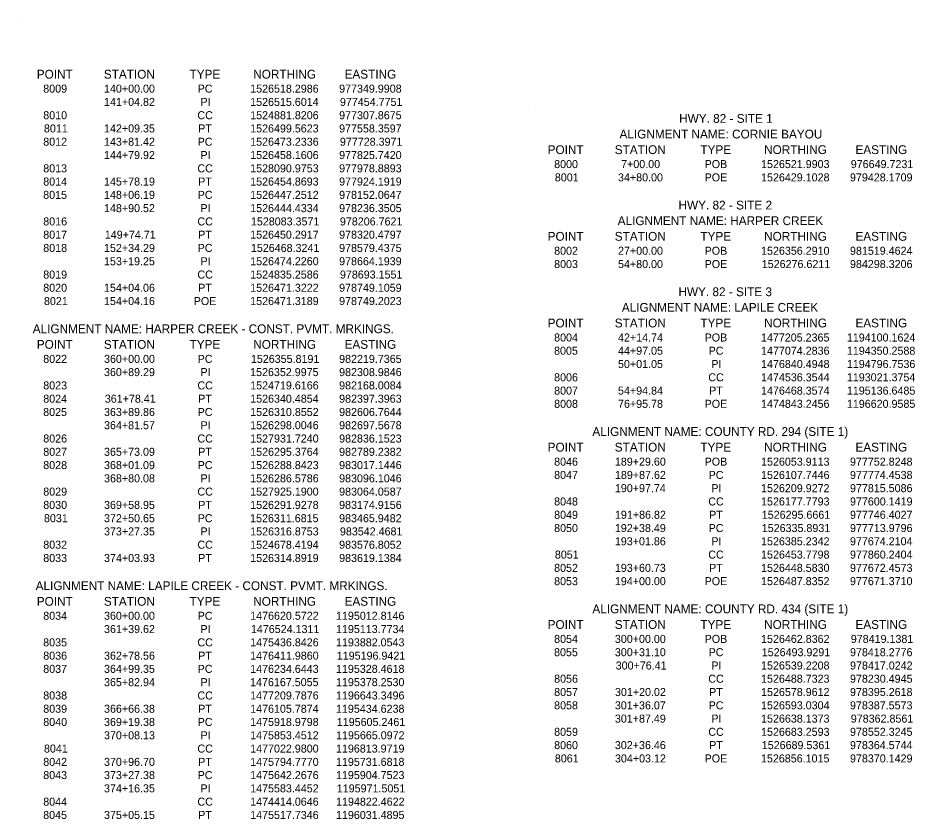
# Model space of a CAD drawing. Extents: x 977669 to 1196358, y 1472413 to 1526490.
# Drawn here: x 1193267 to 1194387, y 1472473 to 1473473 of the extents above; entities that cross this region are included whole.
import ezdxf

# ---------------------------------------------------------------- set-up
doc = ezdxf.new("R2010")
doc.units = 0
doc.layers.add('Default', color=7, linetype='Continuous')
doc.layers.add('R_Border', color=7, linetype='Continuous')

msp = doc.modelspace()

# ---------------------------------------------------------------- linework, layer by layer
at = {"layer": 'R_Border'}
for p, q in [((1193266.6, 1473473.4), (1193266.6, 1473473.4)), ((1193904.8, 1473357.8), (1193904.8, 1473357.8))]:
    msp.add_line(p, q, dxfattribs=at)

# ---------------------------------------------------------------- texts
at = {"layer": 'Default'}
for s, height, p in [('POINT', 11, (1193290.1, 1473397.7)), ('STATION', 11, (1193373.9, 1473397.7)), ('TYPE', 11, (1193480.9, 1473397.7)), ('NORTHING', 11, (1193560.5, 1473397.7)), ('EASTING', 11, (1193674.6, 1473397.7)), ('8009', 10, (1193298.2, 1473380.2)), ('140+00.00', 10, (1193374.1, 1473380.2)), ('PC', 10, (1193491.1, 1473380.2)), ('1526518.2986', 10, (1193556.7, 1473380.2)), ('977349.9908', 10, (1193667.8, 1473380.2)), ('141+04.82', 10, (1193374.1, 1473363.6)), ('PI', 10, (1193494.6, 1473363.6)), ('1526515.6014', 10, (1193556.7, 1473363.6)), ('977454.7751', 10, (1193668.8, 1473363.6)), ('8010', 10, (1193298.2, 1473347)), ('CC', 10, (1193490.8, 1473347)), ('1524881.8206', 10, (1193556.7, 1473347)), ('977307.8675', 10, (1193667.8, 1473347)), ('HWY. 82 - SITE 1', 11, (1194092.6, 1473342.5)), ('8011', 10, (1193299.1, 1473330.5)), ('142+09.35', 10, (1193374.1, 1473330.5)), ('PT', 10, (1193491.8, 1473330.5)), ('1526499.5623', 10, (1193556.7, 1473330.5)), ('977558.3597', 10, (1193667.8, 1473330.5)), ('ALIGNMENT NAME: CORNIE BAYOU', 11, (1194018.1, 1473323)), ('8012', 10, (1193298.2, 1473313.9)), ('143+81.42', 10, (1193374.1, 1473313.9)), ('PC', 10, (1193491.1, 1473313.9)), ('1526473.2336', 10, (1193556.7, 1473313.9)), ('977728.3971', 10, (1193668.8, 1473313.9)), ('POINT', 11, (1193928.3, 1473303.5)), ('STATION', 11, (1194012.1, 1473303.5)), ('TYPE', 11, (1194119.1, 1473303.5)), ('NORTHING', 11, (1194198.7, 1473303.5)), ('EASTING', 11, (1194312.8, 1473303.5)), ('144+79.92', 10, (1193374.1, 1473297.3)), ('PI', 10, (1193494.6, 1473297.3)), ('1526458.1606', 10, (1193556.7, 1473297.3)), ('977825.7420', 10, (1193667.8, 1473297.3)), ('8013', 10, (1193298.2, 1473280.7)), ('CC', 10, (1193490.8, 1473280.7)), ('1528090.9753', 10, (1193556.7, 1473280.7)), ('977978.8893', 10, (1193667.8, 1473280.7)), ('8000', 10, (1193936.4, 1473286)), ('7+00.00', 10, (1194020.1, 1473286)), ('POB', 10, (1194124.4, 1473286)), ('1526521.9903', 10, (1194194.9, 1473286)), ('976649.7231', 10, (1194307, 1473286)), ('8001', 10, (1193937.3, 1473269.4)), ('34+80.00', 10, (1194016.2, 1473269.4)), ('POE', 10, (1194124.4, 1473269.4)), ('1526429.1028', 10, (1194194.9, 1473269.4)), ('979428.1709', 10, (1194306, 1473269.4)), ('8014', 10, (1193298.2, 1473264.2)), ('145+78.19', 10, (1193374.1, 1473264.2)), ('PT', 10, (1193491.8, 1473264.2)), ('1526454.8693', 10, (1193556.7, 1473264.2)), ('977924.1919', 10, (1193667.8, 1473264.2)), ('8015', 10, (1193298.1, 1473247.6)), ('148+06.19', 10, (1193374.1, 1473247.6)), ('PC', 10, (1193491.1, 1473247.6)), ('1526447.2512', 10, (1193556.7, 1473247.6)), ('978152.0647', 10, (1193667.8, 1473247.6)), ('HWY. 82 - SITE 2', 11, (1194091.8, 1473234.3)), ('148+90.52', 10, (1193374.1, 1473231)), ('PI', 10, (1193494.6, 1473231)), ('1526444.4334', 10, (1193556.7, 1473231)), ('978236.3505', 10, (1193667.8, 1473231)), ('8016', 10, (1193298.2, 1473214.4)), ('CC', 10, (1193490.8, 1473214.4)), ('1528083.3571', 10, (1193557.6, 1473214.4)), ('978206.7621', 10, (1193668.8, 1473214.4)), ('ALIGNMENT NAME: HARPER CREEK', 11, (1194015.8, 1473214.8)), ('8017', 10, (1193298.2, 1473197.9)), ('149+74.71', 10, (1193375.1, 1473197.9)), ('PT', 10, (1193491.8, 1473197.9)), ('1526450.2917', 10, (1193556.7, 1473197.9)), ('978320.4797', 10, (1193667.8, 1473197.9)), ('POINT', 11, (1193928.3, 1473195.3)), ('STATION', 11, (1194012.1, 1473195.3)), ('TYPE', 11, (1194119.1, 1473195.3)), ('NORTHING', 11, (1194198.7, 1473195.3)), ('EASTING', 11, (1194312.8, 1473195.3)), ('8018', 10, (1193298.2, 1473181.3)), ('152+34.29', 10, (1193374.1, 1473181.3)), ('PC', 10, (1193491.1, 1473181.3)), ('1526468.3241', 10, (1193557.6, 1473181.3)), ('978579.4375', 10, (1193667.8, 1473181.3)), ('8002', 10, (1193936.4, 1473177.8)), ('27+00.00', 10, (1194016.2, 1473177.8)), ('POB', 10, (1194124.4, 1473177.8)), ('1526356.2910', 10, (1194194.9, 1473177.8)), ('981519.4624', 10, (1194306, 1473177.8)), ('153+19.25', 10, (1193374.1, 1473164.7)), ('PI', 10, (1193494.6, 1473164.7)), ('1526474.2260', 10, (1193556.7, 1473164.7)), ('978664.1939', 10, (1193667.8, 1473164.7)), ('8003', 10, (1193936.4, 1473161.2)), ('54+80.00', 10, (1194016.2, 1473161.2)), ('POE', 10, (1194124.4, 1473161.2)), ('1526276.6211', 10, (1194195.8, 1473161.2)), ('984298.3206', 10, (1194306, 1473161.2)), ('8019', 10, (1193298.2, 1473148.1)), ('CC', 10, (1193490.8, 1473148.1)), ('1524835.2586', 10, (1193556.7, 1473148.1)), ('978693.1551', 10, (1193668.8, 1473148.1)), ('8020', 10, (1193298.2, 1473131.6)), ('154+04.06', 10, (1193374.1, 1473131.6)), ('PT', 10, (1193491.8, 1473131.6)), ('1526471.3222', 10, (1193556.7, 1473131.6)), ('978749.1059', 10, (1193667.8, 1473131.6)), ('HWY. 82 - SITE 3', 11, (1194091.7, 1473126.1)), ('8021', 10, (1193299.1, 1473115)), ('154+04.16', 10, (1193374.1, 1473115)), ('POE', 10, (1193486.2, 1473115)), ('1526471.3189', 10, (1193556.7, 1473115)), ('978749.2023', 10, (1193667.8, 1473115)), ('ALIGNMENT NAME: LAPILE CREEK', 11, (1194021, 1473106.6)), ('ALIGNMENT NAME: HARPER CREEK - CONST. PVMT. MRKINGS.', 11, (1193285.1, 1473079.9)), ('POINT', 11, (1193928.3, 1473087.1)), ('STATION', 11, (1194012.1, 1473087.1)), ('TYPE', 11, (1194119.1, 1473087.1)), ('NORTHING', 11, (1194198.7, 1473087.1)), ('EASTING', 11, (1194312.8, 1473087.1)), ('8004', 10, (1193936.4, 1473069.5)), ('42+14.74', 10, (1194016.2, 1473069.5)), ('POB', 10, (1194124.4, 1473069.5)), ('1477205.2365', 10, (1194194.8, 1473069.5)), ('1194100.1624', 10, (1194302.1, 1473069.5)), ('POINT', 11, (1193290.1, 1473060.4)), ('STATION', 11, (1193373.9, 1473060.4)), ('TYPE', 11, (1193480.9, 1473060.4)), ('NORTHING', 11, (1193560.5, 1473060.4)), ('EASTING', 11, (1193674.6, 1473060.4)), ('8005', 10, (1193936.3, 1473053)), ('44+97.05', 10, (1194016.2, 1473053)), ('PC', 10, (1194129.4, 1473053)), ('1477074.2836', 10, (1194194.9, 1473053)), ('1194350.2588', 10, (1194302.1, 1473053)), ('8022', 10, (1193298.2, 1473042.8)), ('360+00.00', 10, (1193374.1, 1473042.8)), ('PC', 10, (1193491.1, 1473042.8)), ('1526355.8191', 10, (1193557.6, 1473042.8)), ('982219.7365', 10, (1193667.8, 1473042.8)), ('50+01.05', 10, (1194016.2, 1473036.4)), ('PI', 10, (1194132.8, 1473036.4)), ('1476840.4948', 10, (1194194.9, 1473036.4)), ('1194796.7536', 10, (1194302.1, 1473036.4)), ('360+89.29', 10, (1193374.1, 1473026.3)), ('PI', 10, (1193494.6, 1473026.3)), ('1526352.9975', 10, (1193556.6, 1473026.3)), ('982308.9846', 10, (1193667.8, 1473026.3)), ('8006', 10, (1193936.4, 1473019.8)), ('CC', 10, (1194129, 1473019.8)), ('1474536.3544', 10, (1194194.9, 1473019.8)), ('1193021.3754', 10, (1194302.1, 1473019.8)), ('8023', 10, (1193298.2, 1473009.7)), ('CC', 10, (1193490.8, 1473009.7)), ('1524719.6166', 10, (1193556.7, 1473009.7)), ('982168.0084', 10, (1193667.8, 1473009.7)), ('8007', 10, (1193936.4, 1473003.2)), ('54+94.84', 10, (1194016.2, 1473003.2)), ('PT', 10, (1194130, 1473003.2)), ('1476468.3574', 10, (1194194.9, 1473003.2)), ('1195136.6485', 10, (1194302.1, 1473003.2)), ('8024', 10, (1193298.2, 1472993.1)), ('361+78.41', 10, (1193375.1, 1472993.1)), ('PT', 10, (1193491.8, 1472993.1)), ('1526340.4854', 10, (1193556.7, 1472993.1)), ('982397.3963', 10, (1193667.8, 1472993.1)), ('8025', 10, (1193298.1, 1472976.5)), ('363+89.86', 10, (1193374.1, 1472976.5)), ('PC', 10, (1193491.1, 1472976.5)), ('1526310.8552', 10, (1193556.7, 1472976.5)), ('982606.7644', 10, (1193667.8, 1472976.5)), ('8008', 10, (1193936.4, 1472986.7)), ('76+95.78', 10, (1194016.2, 1472986.7)), ('POE', 10, (1194124.4, 1472986.7)), ('1474843.2456', 10, (1194194.9, 1472986.7)), ('1196620.9585', 10, (1194302.1, 1472986.7)), ('364+81.57', 10, (1193374.1, 1472960)), ('PI', 10, (1193494.6, 1472960)), ('1526298.0046', 10, (1193556.7, 1472960)), ('982697.5678', 10, (1193667.8, 1472960)), ('8026', 10, (1193298.2, 1472943.4)), ('CC', 10, (1193490.8, 1472943.4)), ('1527931.7240', 10, (1193556.7, 1472943.4)), ('982836.1523', 10, (1193667.8, 1472943.4)), ('ALIGNMENT NAME: COUNTY RD. 294 (SITE 1)', 11, (1193984.2, 1472951.6)), ('POINT', 11, (1193928.3, 1472932.1)), ('STATION', 11, (1194012.1, 1472932.1)), ('TYPE', 11, (1194119.1, 1472932.1)), ('NORTHING', 11, (1194198.7, 1472932.1)), ('EASTING', 11, (1194312.8, 1472932.1)), ('8027', 10, (1193298.2, 1472926.8)), ('365+73.09', 10, (1193374.1, 1472926.8)), ('PT', 10, (1193491.8, 1472926.8)), ('1526295.3764', 10, (1193556.7, 1472926.8)), ('982789.2382', 10, (1193667.8, 1472926.8)), ('8028', 10, (1193298.2, 1472910.2)), ('368+01.09', 10, (1193374.1, 1472910.2)), ('PC', 10, (1193491.1, 1472910.2)), ('1526288.8423', 10, (1193556.7, 1472910.2)), ('983017.1446', 10, (1193667.8, 1472910.2)), ('8046', 10, (1193936.4, 1472914.5)), ('189+29.60', 10, (1194012.3, 1472914.5)), ('POB', 10, (1194124.4, 1472914.5)), ('1526053.9113', 10, (1194194.9, 1472914.5)), ('977752.8248', 10, (1194306, 1472914.5)), ('8047', 10, (1193936.4, 1472897.9)), ('189+87.62', 10, (1194012.4, 1472897.9)), ('PC', 10, (1194129.4, 1472897.9)), ('1526107.7446', 10, (1194194.9, 1472897.9)), ('977774.4538', 10, (1194306, 1472897.9)), ('368+80.08', 10, (1193374.1, 1472893.7)), ('PI', 10, (1193494.6, 1472893.7)), ('1526286.5786', 10, (1193556.7, 1472893.7)), ('983096.1046', 10, (1193667.8, 1472893.7)), ('8029', 10, (1193298.2, 1472877.1)), ('CC', 10, (1193490.8, 1472877.1)), ('1527925.1900', 10, (1193556.7, 1472877.1)), ('983064.0587', 10, (1193667.8, 1472877.1)), ('190+97.74', 10, (1194012.3, 1472881.4)), ('PI', 10, (1194132.8, 1472881.4)), ('1526209.9272', 10, (1194194.9, 1472881.4)), ('977815.5086', 10, (1194306, 1472881.4)), ('8048', 10, (1193936.4, 1472864.8)), ('CC', 10, (1194129, 1472864.8)), ('1526177.7793', 10, (1194194.9, 1472864.8)), ('977600.1419', 10, (1194306, 1472864.8)), ('8030', 10, (1193298.2, 1472860.5)), ('369+58.95', 10, (1193374.1, 1472860.5)), ('PT', 10, (1193491.8, 1472860.5)), ('1526291.9278', 10, (1193556.7, 1472860.5)), ('983174.9156', 10, (1193667.8, 1472860.5)), ('8031', 10, (1193299.1, 1472843.9)), ('372+50.65', 10, (1193374.1, 1472843.9)), ('PC', 10, (1193491.1, 1472843.9)), ('1526311.6815', 10, (1193556.6, 1472843.9)), ('983465.9482', 10, (1193667.8, 1472843.9)), ('8049', 10, (1193936.4, 1472848.2)), ('191+86.82', 10, (1194012.4, 1472848.2)), ('PT', 10, (1194130, 1472848.2)), ('1526295.6661', 10, (1194195.8, 1472848.2)), ('977746.4027', 10, (1194306, 1472848.2)), ('8050', 10, (1193936.4, 1472831.6)), ('192+38.49', 10, (1194012.3, 1472831.6)), ('PC', 10, (1194129.4, 1472831.6)), ('1526335.8931', 10, (1194195.8, 1472831.6)), ('977713.9796', 10, (1194306, 1472831.6)), ('373+27.35', 10, (1193374.1, 1472827.4)), ('PI', 10, (1193494.6, 1472827.4)), ('1526316.8753', 10, (1193556.7, 1472827.4)), ('983542.4681', 10, (1193668.8, 1472827.4)), ('8032', 10, (1193298.2, 1472810.8)), ('CC', 10, (1193490.8, 1472810.8)), ('1524678.4194', 10, (1193556.7, 1472810.8)), ('983576.8052', 10, (1193667.8, 1472810.8)), ('193+01.86', 10, (1194012.3, 1472815.1)), ('PI', 10, (1194132.8, 1472815.1)), ('1526385.2342', 10, (1194194.9, 1472815.1)), ('977674.2104', 10, (1194306, 1472815.1)), ('8051', 10, (1193937.3, 1472798.5)), ('CC', 10, (1194129, 1472798.5)), ('1526453.7798', 10, (1194194.9, 1472798.5)), ('977860.2404', 10, (1194306, 1472798.5)), ('8033', 10, (1193298.2, 1472794.2)), ('374+03.93', 10, (1193374.1, 1472794.2)), ('PT', 10, (1193491.8, 1472794.2)), ('1526314.8919', 10, (1193556.7, 1472794.2)), ('983619.1384', 10, (1193667.8, 1472794.2)), ('8052', 10, (1193936.4, 1472781.9)), ('193+60.73', 10, (1194012.3, 1472781.9)), ('PT', 10, (1194130, 1472781.9)), ('1526448.5830', 10, (1194194.9, 1472781.9)), ('977672.4573', 10, (1194306, 1472781.9)), ('8053', 10, (1193936.4, 1472765.3)), ('194+00.00', 10, (1194012.3, 1472765.3)), ('POE', 10, (1194124.4, 1472765.3)), ('1526487.8352', 10, (1194194.9, 1472765.3)), ('977671.3710', 10, (1194306, 1472765.3)), ('ALIGNMENT NAME: LAPILE CREEK - CONST. PVMT. MRKINGS.', 11, (1193288.7, 1472759.1)), ('POINT', 11, (1193290.1, 1472739.6)), ('STATION', 11, (1193373.9, 1472739.6)), ('TYPE', 11, (1193480.9, 1472739.6)), ('NORTHING', 11, (1193560.5, 1472739.6)), ('EASTING', 11, (1193674.6, 1472739.6)), ('ALIGNMENT NAME: COUNTY RD. 434 (SITE 1)', 11, (1193984.2, 1472730.2)), ('8034', 10, (1193298.2, 1472722.1)), ('360+00.00', 10, (1193374.1, 1472722.1)), ('PC', 10, (1193491.1, 1472722.1)), ('1476620.5722', 10, (1193556.7, 1472722.1)), ('1195012.8146', 10, (1193663.9, 1472722.1)), ('POINT', 11, (1193928.3, 1472710.7)), ('STATION', 11, (1194012.1, 1472710.7)), ('TYPE', 11, (1194119.1, 1472710.7)), ('NORTHING', 11, (1194198.7, 1472710.7)), ('EASTING', 11, (1194312.8, 1472710.7)), ('361+39.62', 10, (1193374.1, 1472705.5)), ('PI', 10, (1193494.6, 1472705.5)), ('1476524.1311', 10, (1193557.6, 1472705.5)), ('1195113.7734', 10, (1193663.9, 1472705.5)), ('8035', 10, (1193298.1, 1472688.9)), ('CC', 10, (1193490.8, 1472688.9)), ('1475436.8426', 10, (1193556.7, 1472688.9)), ('1193882.0543', 10, (1193663.9, 1472688.9)), ('8054', 10, (1193936.4, 1472693.2)), ('300+00.00', 10, (1194012.3, 1472693.2)), ('POB', 10, (1194124.4, 1472693.2)), ('1526462.8362', 10, (1194194.9, 1472693.2)), ('978419.1381', 10, (1194307, 1472693.2)), ('8055', 10, (1193936.3, 1472676.6)), ('300+31.10', 10, (1194012.3, 1472676.6)), ('PC', 10, (1194129.4, 1472676.6)), ('1526493.9291', 10, (1194195.8, 1472676.6)), ('978418.2776', 10, (1194306, 1472676.6)), ('8036', 10, (1193298.2, 1472672.3)), ('362+78.56', 10, (1193374.1, 1472672.3)), ('PT', 10, (1193491.8, 1472672.3)), ('1476411.9860', 10, (1193556.7, 1472672.3)), ('1195196.9421', 10, (1193664.9, 1472672.3)), ('8037', 10, (1193298.2, 1472655.8)), ('364+99.35', 10, (1193374.1, 1472655.8)), ('PC', 10, (1193491.1, 1472655.8)), ('1476234.6443', 10, (1193556.7, 1472655.8)), ('1195328.4618', 10, (1193663.9, 1472655.8)), ('300+76.41', 10, (1194013.3, 1472660)), ('PI', 10, (1194132.8, 1472660)), ('1526539.2208', 10, (1194194.9, 1472660)), ('978417.0242', 10, (1194306.1, 1472660)), ('8056', 10, (1193936.4, 1472643.5)), ('CC', 10, (1194129, 1472643.5)), ('1526488.7323', 10, (1194194.9, 1472643.5)), ('978230.4945', 10, (1194306, 1472643.5)), ('365+82.94', 10, (1193374.1, 1472639.2)), ('PI', 10, (1193494.6, 1472639.2)), ('1476167.5055', 10, (1193556.6, 1472639.2)), ('1195378.2530', 10, (1193663.9, 1472639.2)), ('8038', 10, (1193298.2, 1472622.6)), ('CC', 10, (1193490.8, 1472622.6)), ('1477209.7876', 10, (1193556.7, 1472622.6)), ('1196643.3496', 10, (1193663.9, 1472622.6)), ('8057', 10, (1193936.4, 1472626.9)), ('301+20.02', 10, (1194012.4, 1472626.9)), ('PT', 10, (1194130, 1472626.9)), ('1526578.9612', 10, (1194194.9, 1472626.9)), ('978395.2618', 10, (1194306, 1472626.9)), ('8058', 10, (1193936.4, 1472610.3)), ('301+36.07', 10, (1194012.3, 1472610.3)), ('PC', 10, (1194129.4, 1472610.3)), ('1526593.0304', 10, (1194194.9, 1472610.3)), ('978387.5573', 10, (1194306, 1472610.3)), ('8039', 10, (1193298.2, 1472606)), ('366+66.38', 10, (1193374.1, 1472606)), ('PT', 10, (1193491.8, 1472606)), ('1476105.7874', 10, (1193556.7, 1472606)), ('1195434.6238', 10, (1193663.9, 1472606)), ('8040', 10, (1193298.2, 1472589.5)), ('369+19.38', 10, (1193374.1, 1472589.5)), ('PC', 10, (1193491.1, 1472589.5)), ('1475918.9798', 10, (1193556.7, 1472589.5)), ('1195605.2461', 10, (1193664.9, 1472589.5)), ('301+87.49', 10, (1194012.3, 1472593.7)), ('PI', 10, (1194132.8, 1472593.7)), ('1526638.1373', 10, (1194194.9, 1472593.7)), ('978362.8561', 10, (1194307, 1472593.7)), ('370+08.13', 10, (1193374.1, 1472572.9)), ('1475853.4512', 10, (1193556.7, 1472572.9)), ('1195665.0972', 10, (1193664, 1472572.9)), ('8059', 10, (1193936.4, 1472577.2)), ('CC', 10, (1194129, 1472577.2)), ('1526683.2593', 10, (1194194.9, 1472577.2)), ('978552.3245', 10, (1194306, 1472577.2)), ('PI', 10, (1193494.6, 1472572.9)), ('8041', 10, (1193299.1, 1472556.3)), ('CC', 10, (1193490.8, 1472556.3)), ('1477022.9800', 10, (1193556.7, 1472556.3)), ('1196813.9719', 10, (1193663.9, 1472556.3)), ('8060', 10, (1193936.4, 1472560.6)), ('302+36.46', 10, (1194012.3, 1472560.6)), ('PT', 10, (1194130, 1472560.6)), ('1526689.5361', 10, (1194195.8, 1472560.6)), ('978364.5744', 10, (1194306, 1472560.6)), ('8042', 10, (1193298.2, 1472539.7)), ('370+96.70', 10, (1193374.1, 1472539.7)), ('PT', 10, (1193491.8, 1472539.7)), ('1475794.7770', 10, (1193556.7, 1472539.7)), ('1195731.6818', 10, (1193663.9, 1472539.7)), ('8061', 10, (1193937.3, 1472544)), ('304+03.12', 10, (1194012.4, 1472544)), ('POE', 10, (1194124.4, 1472544)), ('1526856.1015', 10, (1194194.8, 1472544)), ('978370.1429', 10, (1194306, 1472544)), ('8043', 10, (1193298.2, 1472523.2)), ('373+27.38', 10, (1193374.1, 1472523.2)), ('PC', 10, (1193491.1, 1472523.2)), ('1475642.2676', 10, (1193556.7, 1472523.2)), ('1195904.7523', 10, (1193663.9, 1472523.2)), ('374+16.35', 10, (1193374.1, 1472506.6)), ('PI', 10, (1193494.6, 1472506.6)), ('1475583.4452', 10, (1193556.7, 1472506.6)), ('1195971.5051', 10, (1193664.9, 1472506.6)), ('8044', 10, (1193298.2, 1472490)), ('CC', 10, (1193490.8, 1472490)), ('1474414.0646', 10, (1193556.7, 1472490)), ('1194822.4622', 10, (1193664, 1472490)), ('8045', 10, (1193298.1, 1472473.4)), ('375+05.15', 10, (1193374.1, 1472473.4)), ('PT', 10, (1193491.8, 1472473.4)), ('1475517.7346', 10, (1193556.7, 1472473.4)), ('1196031.4895', 10, (1193663.9, 1472473.4))]:
    msp.add_text(s, height=height, dxfattribs=at).set_placement(p)

doc.saveas('drawing.dxf')
